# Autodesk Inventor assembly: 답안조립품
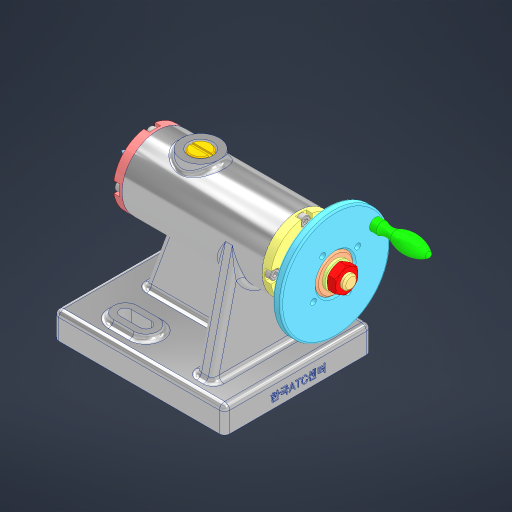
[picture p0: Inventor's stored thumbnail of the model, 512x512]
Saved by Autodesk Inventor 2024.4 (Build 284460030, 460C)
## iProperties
Created: 2026-09
Part Number: 답안조립품
Document SubType Name: Assembly
Designer: user
Author: user
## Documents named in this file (18)
- C:\Users\user\Desktop\760903V1007\답안조립품.iam
- D:\PM 06;50 [평일반] 김민준 [2026-07-14종강]\인벤터2급\2011-08-27 2급 기출문제\메인기어\핸들\핸들.ipt
- D:\PM 06;50 [평일반] 김민준 [2026-07-14종강]\인벤터2급\2011-08-27 2급 기출문제\메인기어\플랜지\플랜지.ipt
- D:\PM 06;50 [평일반] 김민준 [2026-07-14종강]\인벤터2급\2011-08-27 2급 기출문제\메인기어\평행 키 4x4x10\평행 키 4x4x10.ipt
- D:\PM 06;50 [평일반] 김민준 [2026-07-14종강]\인벤터2급\2011-08-27 2급 기출문제\메인기어\평 와셔 M8\평 와셔 M8.ipt
- D:\PM 06;50 [평일반] 김민준 [2026-07-14종강]\인벤터2급\2011-08-27 2급 기출문제\메인기어\커버\커버.ipt
- D:\PM 06;50 [평일반] 김민준 [2026-07-14종강]\인벤터2급\2011-08-27 2급 기출문제\메인기어\슬리브\슬리브.ipt
- D:\PM 06;50 [평일반] 김민준 [2026-07-14종강]\인벤터2급\2011-08-27 2급 기출문제\메인기어\스톱퍼\스톱퍼.ipt
- D:\PM 06;50 [평일반] 김민준 [2026-07-14종강]\인벤터2급\2011-08-27 2급 기출문제\메인기어\센터홀더\센터홀더.ipt
- D:\PM 06;50 [평일반] 김민준 [2026-07-14종강]\인벤터2급\2011-08-27 2급 기출문제\메인기어\센터\센터.ipt
- D:\PM 06;50 [평일반] 김민준 [2026-07-14종강]\인벤터2급\2011-08-27 2급 기출문제\메인기어\부시\부시.ipt
- D:\PM 06;50 [평일반] 김민준 [2026-07-14종강]\인벤터2급\2011-08-27 2급 기출문제\메인기어\멈춤나사 M3\멈춤나사 M3.ipt
- D:\PM 06;50 [평일반] 김민준 [2026-07-14종강]\인벤터2급\2011-08-27 2급 기출문제\메인기어\돌림판\돌림판.ipt
- D:\PM 06;50 [평일반] 김민준 [2026-07-14종강]\인벤터2급\2011-08-27 2급 기출문제\메인기어\나사축\나사축.ipt
- D:\PM 06;50 [평일반] 김민준 [2026-07-14종강]\인벤터2급\2011-08-27 2급 기출문제\메인기어\가이드 부시\가이드 부시.ipt
- D:\PM 06;50 [평일반] 김민준 [2026-07-14종강]\인벤터2급\2011-08-27 2급 기출문제\메인기어\6각 너트 M8\6각 너트 M8.ipt
- D:\PM 06;50 [평일반] 김민준 [2026-07-14종강]\인벤터2급\2011-08-27 2급 기출문제\메인기어\6각 구멍붙이 볼트 M3x8\6각 구멍붙이 볼트 M3x8.ipt
- C:\Users\user\Desktop\760903V1007\본체.ipt
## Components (12 placed, 5 different names)
1. 핸들:1
2. 플랜지:1
3. 가이드 부시:1 — 플러쉬:2
4. 6각 너트 M8:1
5. 6각 구멍붙이 볼트 M3x8:1
6. 6각 구멍붙이 볼트 M3x8:2
7. 6각 구멍붙이 볼트 M3x8:3
8. 6각 구멍붙이 볼트 M3x8:4
9. 6각 구멍붙이 볼트 M3x8:5
10. 6각 구멍붙이 볼트 M3x8:6
11. 6각 구멍붙이 볼트 M3x8:7
12. 6각 구멍붙이 볼트 M3x8:8
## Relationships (1: Flush 1)
- 플러쉬:2 [Flush]: 가이드 부시:1
